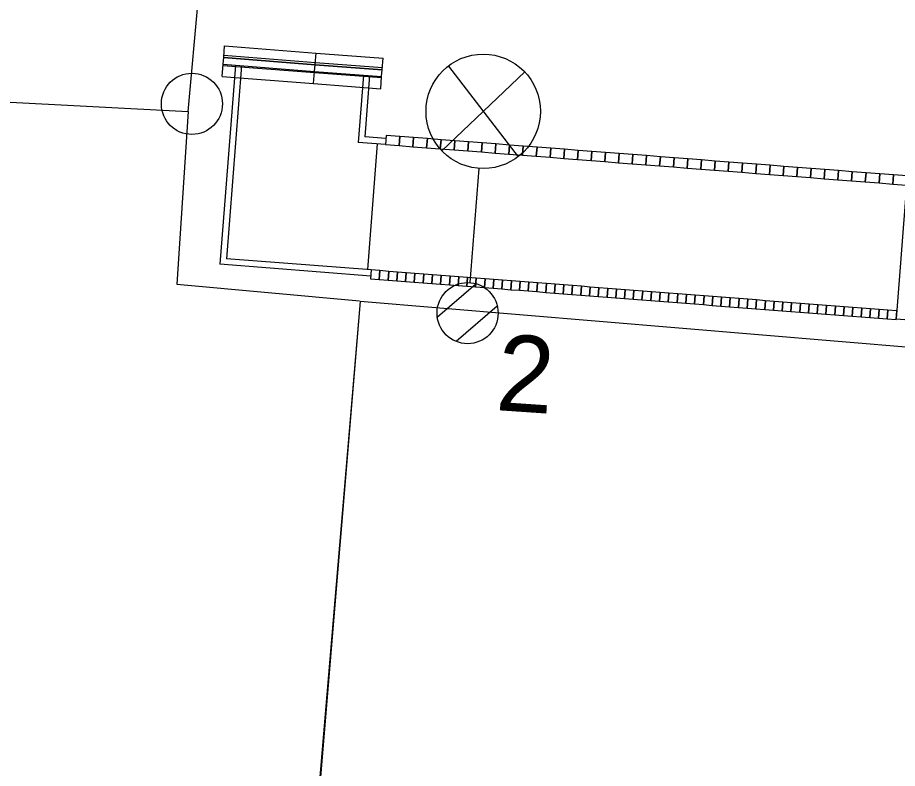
# Model space of a CAD drawing. Extents: x -669628 to -669207, y -977198 to -977075.
# Drawn here: x -669522.25 to -669510.73, y -977152.89 to -977143.06 of the extents above; entities that cross this region are included whole.
import ezdxf

# ---------------------------------------------------------------- set-up
doc = ezdxf.new("R2010")
doc.units = 0
for name, color, linetype in [('SO 01-86-01', 7, 'Continuous'), ('SO 11-11-01', 7, 'Continuous'), ('SO 11-12-01', 7, 'Continuous')]:
    doc.layers.add(name, color=color, linetype=linetype)

# ---------------------------------------------------------------- blocks, each defined once
blk = doc.blocks.new('POINT_DISPLAY')
blk.add_line((0, 0), (0, 0))

msp = doc.modelspace()

# ---------------------------------------------------------------- linework, layer by layer
at = {"layer": 'SO 01-86-01'}
for p, q in [((-669520.014, -977144.295), (-669519.163, -977134.751)), ((-669539.545, -977143.259), (-669520.014, -977144.295)), ((-669516.607, -977143.698), (-669515.695, -977144.885)), ((-669516.693, -977144.807), (-669515.608, -977143.775)), ((-669520.014, -977144.295), (-669520.162, -977146.551)), ((-669516.209, -977145.037), (-669516.325, -977146.533)), ((-669520.162, -977146.551), (-669517.772, -977146.771)), ((-669516.75, -977146.981), (-669516.246, -977146.55)), ((-669517.763, -977146.78), (-669518.52, -977155.707)), ((-669517.763, -977146.78), (-669518.507, -977155.699)), ((-669517.763, -977146.78), (-669518.424, -977154.562)), ((-669445.341, -977152.857), (-669517.763, -977146.78)), ((-669445.341, -977152.857), (-669517.763, -977146.78)), ((-669443.485, -977152.976), (-669517.763, -977146.78)), ((-669516.506, -977147.298), (-669515.969, -977146.838))]:
    msp.add_line(p, q, dxfattribs=at)
for centre, radius in [((-669516.151, -977144.291), 0.749), ((-669519.965, -977144.193), 0.4), ((-669516.356, -977146.932), 0.4)]:
    msp.add_circle(centre, radius, dxfattribs=at)
at = {"layer": 'SO 11-11-01'}
for p, q in [((-669519.548, -977143.584), (-669519.536, -977143.435)), ((-669519.536, -977143.435), (-669518.34, -977143.529)), ((-669518.351, -977143.677), (-669518.34, -977143.529)), ((-669518.351, -977143.677), (-669518.34, -977143.529)), ((-669518.34, -977143.529), (-669517.462, -977143.597)), ((-669519.555, -977143.675), (-669519.548, -977143.584)), ((-669519.548, -977143.584), (-669518.351, -977143.677)), ((-669519.548, -977143.588), (-669518.352, -977143.681)), ((-669519.546, -977143.558), (-669518.349, -977143.651)), ((-669518.349, -977143.651), (-669517.472, -977143.719)), ((-669517.474, -977143.745), (-669517.462, -977143.597)), ((-669519.567, -977143.834), (-669519.555, -977143.675)), ((-669519.556, -977143.689), (-669518.359, -977143.782)), ((-669519.555, -977143.675), (-669518.358, -977143.768)), ((-669518.358, -977143.768), (-669518.351, -977143.677)), ((-669518.358, -977143.768), (-669518.351, -977143.677)), ((-669518.352, -977143.681), (-669517.474, -977143.749)), ((-669518.351, -977143.677), (-669517.474, -977143.745)), ((-669517.481, -977143.836), (-669517.474, -977143.745)), ((-669519.567, -977143.834), (-669518.371, -977143.927)), ((-669518.371, -977143.927), (-669518.358, -977143.768)), ((-669518.371, -977143.927), (-669518.358, -977143.768)), ((-669518.359, -977143.782), (-669517.482, -977143.85)), ((-669518.358, -977143.768), (-669517.481, -977143.836)), ((-669517.493, -977143.996), (-669517.481, -977143.836)), ((-669518.371, -977143.927), (-669517.493, -977143.996))]:
    msp.add_line(p, q, dxfattribs=at)
at = {"layer": 'SO 11-12-01'}
for p, q in [((-669519.395, -977143.687), (-669519.598, -977146.293)), ((-669519.315, -977143.693), (-669519.512, -977146.22)), ((-669517.72, -977143.818), (-669517.789, -977144.698)), ((-669517.641, -977143.824), (-669517.703, -977144.624)), ((-669510.545, -977144.409), (-669510.747, -977147.008)), ((-669517.425, -977144.646), (-669517.703, -977144.624)), ((-669517.421, -977144.606), (-669517.431, -977144.726)), ((-669517.242, -977144.62), (-669517.421, -977144.606)), ((-669517.251, -977144.74), (-669517.242, -977144.62)), ((-669517.242, -977144.62), (-669517.251, -977144.74)), ((-669517.062, -977144.634), (-669517.242, -977144.62)), ((-669517.072, -977144.754), (-669517.062, -977144.634)), ((-669517.062, -977144.634), (-669517.072, -977144.754)), ((-669516.883, -977144.648), (-669517.062, -977144.634)), ((-669516.892, -977144.768), (-669516.883, -977144.648)), ((-669516.883, -977144.648), (-669516.892, -977144.768)), ((-669516.704, -977144.662), (-669516.883, -977144.648)), ((-669516.713, -977144.781), (-669516.704, -977144.662)), ((-669516.704, -977144.662), (-669516.713, -977144.781)), ((-669516.524, -977144.676), (-669516.704, -977144.662)), ((-669516.524, -977144.676), (-669516.533, -977144.795)), ((-669516.533, -977144.795), (-669516.524, -977144.676)), ((-669516.345, -977144.69), (-669516.524, -977144.676)), ((-669517.431, -977144.726), (-669517.789, -977144.698)), ((-669517.54, -977144.717), (-669517.668, -977146.363)), ((-669517.431, -977144.726), (-669517.251, -977144.74)), ((-669517.251, -977144.74), (-669517.072, -977144.754)), ((-669517.072, -977144.754), (-669516.892, -977144.768)), ((-669516.892, -977144.768), (-669516.713, -977144.781)), ((-669516.713, -977144.781), (-669516.533, -977144.795)), ((-669516.533, -977144.795), (-669516.354, -977144.809)), ((-669516.345, -977144.69), (-669516.354, -977144.809)), ((-669516.354, -977144.809), (-669516.345, -977144.69)), ((-669516.165, -977144.704), (-669516.345, -977144.69)), ((-669516.165, -977144.704), (-669516.175, -977144.823)), ((-669516.175, -977144.823), (-669516.165, -977144.704)), ((-669515.986, -977144.718), (-669516.165, -977144.704)), ((-669515.986, -977144.718), (-669515.995, -977144.837)), ((-669515.995, -977144.837), (-669515.986, -977144.718)), ((-669515.806, -977144.732), (-669515.986, -977144.718)), ((-669515.806, -977144.732), (-669515.816, -977144.851)), ((-669515.816, -977144.851), (-669515.806, -977144.732)), ((-669515.627, -977144.746), (-669515.806, -977144.732)), ((-669515.627, -977144.746), (-669515.636, -977144.865)), ((-669515.636, -977144.865), (-669515.627, -977144.746)), ((-669515.447, -977144.76), (-669515.627, -977144.746)), ((-669515.447, -977144.76), (-669515.457, -977144.879)), ((-669515.457, -977144.879), (-669515.447, -977144.76)), ((-669515.268, -977144.774), (-669515.447, -977144.76)), ((-669515.268, -977144.774), (-669515.277, -977144.893)), ((-669515.277, -977144.893), (-669515.268, -977144.774)), ((-669515.088, -977144.788), (-669515.268, -977144.774)), ((-669515.088, -977144.788), (-669515.098, -977144.907)), ((-669515.098, -977144.907), (-669515.088, -977144.788)), ((-669514.909, -977144.802), (-669515.088, -977144.788)), ((-669514.909, -977144.802), (-669514.918, -977144.921)), ((-669514.918, -977144.921), (-669514.909, -977144.802)), ((-669514.73, -977144.816), (-669514.909, -977144.802)), ((-669516.354, -977144.809), (-669516.175, -977144.823)), ((-669516.175, -977144.823), (-669515.995, -977144.837)), ((-669515.995, -977144.837), (-669515.816, -977144.851)), ((-669515.816, -977144.851), (-669515.636, -977144.865)), ((-669515.636, -977144.865), (-669515.457, -977144.879)), ((-669515.457, -977144.879), (-669515.277, -977144.893)), ((-669515.277, -977144.893), (-669515.098, -977144.907)), ((-669515.098, -977144.907), (-669514.918, -977144.921)), ((-669514.73, -977144.816), (-669514.739, -977144.935)), ((-669514.739, -977144.935), (-669514.73, -977144.816)), ((-669514.55, -977144.829), (-669514.73, -977144.816)), ((-669514.55, -977144.829), (-669514.559, -977144.949)), ((-669514.559, -977144.949), (-669514.55, -977144.829)), ((-669514.371, -977144.843), (-669514.55, -977144.829)), ((-669514.371, -977144.843), (-669514.38, -977144.963)), ((-669514.38, -977144.963), (-669514.371, -977144.843)), ((-669514.191, -977144.857), (-669514.371, -977144.843)), ((-669514.191, -977144.857), (-669514.2, -977144.977)), ((-669514.2, -977144.977), (-669514.191, -977144.857)), ((-669514.012, -977144.871), (-669514.191, -977144.857)), ((-669514.012, -977144.871), (-669514.021, -977144.991)), ((-669514.021, -977144.991), (-669514.012, -977144.871)), ((-669513.832, -977144.885), (-669514.012, -977144.871)), ((-669513.832, -977144.885), (-669513.842, -977145.005)), ((-669513.842, -977145.005), (-669513.832, -977144.885)), ((-669513.653, -977144.899), (-669513.832, -977144.885)), ((-669513.653, -977144.899), (-669513.662, -977145.019)), ((-669513.662, -977145.019), (-669513.653, -977144.899)), ((-669513.473, -977144.913), (-669513.653, -977144.899)), ((-669513.473, -977144.913), (-669513.483, -977145.033)), ((-669513.483, -977145.033), (-669513.473, -977144.913)), ((-669513.294, -977144.927), (-669513.473, -977144.913)), ((-669514.918, -977144.921), (-669514.739, -977144.935)), ((-669514.739, -977144.935), (-669514.559, -977144.949)), ((-669514.559, -977144.949), (-669514.38, -977144.963)), ((-669514.38, -977144.963), (-669514.2, -977144.977)), ((-669514.2, -977144.977), (-669514.021, -977144.991)), ((-669514.021, -977144.991), (-669513.842, -977145.005)), ((-669513.842, -977145.005), (-669513.662, -977145.019)), ((-669513.662, -977145.019), (-669513.483, -977145.033)), ((-669513.483, -977145.033), (-669513.303, -977145.047)), ((-669513.294, -977144.927), (-669513.303, -977145.047)), ((-669513.303, -977145.047), (-669513.294, -977144.927)), ((-669513.114, -977144.941), (-669513.294, -977144.927)), ((-669513.114, -977144.941), (-669513.124, -977145.061)), ((-669513.124, -977145.061), (-669513.114, -977144.941)), ((-669512.935, -977144.955), (-669513.114, -977144.941)), ((-669512.935, -977144.955), (-669512.944, -977145.075)), ((-669512.944, -977145.075), (-669512.935, -977144.955)), ((-669512.756, -977144.969), (-669512.935, -977144.955)), ((-669512.756, -977144.969), (-669512.765, -977145.089)), ((-669512.765, -977145.089), (-669512.756, -977144.969)), ((-669512.576, -977144.983), (-669512.756, -977144.969)), ((-669512.576, -977144.983), (-669512.585, -977145.103)), ((-669512.585, -977145.103), (-669512.576, -977144.983)), ((-669512.397, -977144.997), (-669512.576, -977144.983)), ((-669512.397, -977144.997), (-669512.406, -977145.117)), ((-669512.406, -977145.117), (-669512.397, -977144.997)), ((-669512.217, -977145.011), (-669512.397, -977144.997)), ((-669512.217, -977145.011), (-669512.226, -977145.131)), ((-669512.226, -977145.131), (-669512.217, -977145.011)), ((-669512.038, -977145.025), (-669512.217, -977145.011)), ((-669512.038, -977145.025), (-669512.047, -977145.145)), ((-669512.047, -977145.145), (-669512.038, -977145.025)), ((-669511.858, -977145.039), (-669512.038, -977145.025)), ((-669513.303, -977145.047), (-669513.124, -977145.061)), ((-669513.124, -977145.061), (-669512.944, -977145.075)), ((-669512.944, -977145.075), (-669512.765, -977145.089)), ((-669512.765, -977145.089), (-669512.585, -977145.103)), ((-669512.585, -977145.103), (-669512.406, -977145.117)), ((-669512.406, -977145.117), (-669512.226, -977145.131)), ((-669512.226, -977145.131), (-669512.047, -977145.145)), ((-669512.047, -977145.145), (-669511.868, -977145.159)), ((-669511.858, -977145.039), (-669511.868, -977145.159)), ((-669511.868, -977145.159), (-669511.858, -977145.039)), ((-669511.679, -977145.053), (-669511.858, -977145.039)), ((-669511.679, -977145.053), (-669511.688, -977145.173)), ((-669511.688, -977145.173), (-669511.679, -977145.053)), ((-669511.499, -977145.067), (-669511.679, -977145.053)), ((-669511.499, -977145.067), (-669511.509, -977145.187)), ((-669511.509, -977145.187), (-669511.499, -977145.067)), ((-669511.32, -977145.081), (-669511.499, -977145.067)), ((-669511.32, -977145.081), (-669511.329, -977145.201)), ((-669511.329, -977145.201), (-669511.32, -977145.081)), ((-669511.14, -977145.095), (-669511.32, -977145.081)), ((-669511.14, -977145.095), (-669511.15, -977145.215)), ((-669511.15, -977145.215), (-669511.14, -977145.095)), ((-669510.961, -977145.109), (-669511.14, -977145.095)), ((-669510.961, -977145.109), (-669510.97, -977145.228)), ((-669510.97, -977145.228), (-669510.961, -977145.109)), ((-669510.781, -977145.123), (-669510.961, -977145.109)), ((-669510.781, -977145.123), (-669510.791, -977145.242)), ((-669510.791, -977145.242), (-669510.781, -977145.123)), ((-669510.602, -977145.137), (-669510.781, -977145.123)), ((-669511.868, -977145.159), (-669511.688, -977145.173)), ((-669511.688, -977145.173), (-669511.509, -977145.187)), ((-669511.509, -977145.187), (-669511.329, -977145.201)), ((-669511.329, -977145.201), (-669511.15, -977145.215)), ((-669511.15, -977145.215), (-669510.97, -977145.228)), ((-669510.97, -977145.228), (-669510.791, -977145.242)), ((-669510.791, -977145.242), (-669510.611, -977145.256)), ((-669517.624, -977146.447), (-669519.598, -977146.293)), ((-669517.618, -977146.367), (-669519.512, -977146.22)), ((-669517.618, -977146.367), (-669517.627, -977146.482)), ((-669517.503, -977146.376), (-669517.618, -977146.367)), ((-669517.503, -977146.376), (-669517.512, -977146.491)), ((-669517.512, -977146.491), (-669517.503, -977146.376)), ((-669517.389, -977146.385), (-669517.503, -977146.376)), ((-669517.389, -977146.385), (-669517.397, -977146.5)), ((-669517.397, -977146.5), (-669517.389, -977146.385)), ((-669517.274, -977146.394), (-669517.389, -977146.385)), ((-669517.274, -977146.394), (-669517.283, -977146.509)), ((-669517.283, -977146.509), (-669517.274, -977146.394)), ((-669517.159, -977146.403), (-669517.274, -977146.394)), ((-669517.159, -977146.403), (-669517.168, -977146.517)), ((-669517.168, -977146.517), (-669517.159, -977146.403)), ((-669517.045, -977146.412), (-669517.159, -977146.403)), ((-669517.045, -977146.412), (-669517.054, -977146.526)), ((-669517.054, -977146.526), (-669517.045, -977146.412)), ((-669516.93, -977146.421), (-669517.045, -977146.412)), ((-669517.627, -977146.482), (-669517.512, -977146.491)), ((-669517.512, -977146.491), (-669517.397, -977146.5)), ((-669517.397, -977146.5), (-669517.283, -977146.509)), ((-669517.283, -977146.509), (-669517.168, -977146.517)), ((-669517.168, -977146.517), (-669517.054, -977146.526)), ((-669517.054, -977146.526), (-669516.939, -977146.535)), ((-669516.939, -977146.535), (-669516.93, -977146.421)), ((-669516.93, -977146.421), (-669516.939, -977146.535)), ((-669516.815, -977146.43), (-669516.93, -977146.421)), ((-669516.824, -977146.544), (-669516.815, -977146.43)), ((-669516.815, -977146.43), (-669516.824, -977146.544)), ((-669516.701, -977146.438), (-669516.815, -977146.43)), ((-669516.71, -977146.553), (-669516.701, -977146.438)), ((-669516.701, -977146.438), (-669516.71, -977146.553)), ((-669516.586, -977146.447), (-669516.701, -977146.438)), ((-669516.595, -977146.562), (-669516.586, -977146.447)), ((-669516.586, -977146.447), (-669516.595, -977146.562)), ((-669516.471, -977146.456), (-669516.586, -977146.447)), ((-669516.48, -977146.571), (-669516.471, -977146.456)), ((-669516.471, -977146.456), (-669516.48, -977146.571)), ((-669516.357, -977146.465), (-669516.471, -977146.456)), ((-669516.366, -977146.58), (-669516.357, -977146.465)), ((-669516.357, -977146.465), (-669516.366, -977146.58)), ((-669516.242, -977146.474), (-669516.357, -977146.465)), ((-669516.251, -977146.589), (-669516.242, -977146.474)), ((-669516.242, -977146.474), (-669516.251, -977146.589)), ((-669516.127, -977146.483), (-669516.242, -977146.474)), ((-669516.136, -977146.598), (-669516.127, -977146.483)), ((-669516.127, -977146.483), (-669516.136, -977146.598)), ((-669516.013, -977146.492), (-669516.127, -977146.483)), ((-669516.022, -977146.607), (-669516.013, -977146.492)), ((-669516.013, -977146.492), (-669516.022, -977146.607)), ((-669515.898, -977146.501), (-669516.013, -977146.492)), ((-669515.907, -977146.616), (-669515.898, -977146.501)), ((-669515.898, -977146.501), (-669515.907, -977146.616)), ((-669515.783, -977146.51), (-669515.898, -977146.501)), ((-669515.792, -977146.625), (-669515.783, -977146.51)), ((-669515.783, -977146.51), (-669515.792, -977146.625)), ((-669515.669, -977146.519), (-669515.783, -977146.51)), ((-669515.678, -977146.633), (-669515.669, -977146.519)), ((-669515.669, -977146.519), (-669515.678, -977146.633)), ((-669515.554, -977146.528), (-669515.669, -977146.519)), ((-669515.563, -977146.642), (-669515.554, -977146.528)), ((-669515.554, -977146.528), (-669515.563, -977146.642)), ((-669515.439, -977146.537), (-669515.554, -977146.528)), ((-669516.939, -977146.535), (-669516.824, -977146.544)), ((-669516.824, -977146.544), (-669516.71, -977146.553)), ((-669516.71, -977146.553), (-669516.595, -977146.562)), ((-669516.595, -977146.562), (-669516.48, -977146.571)), ((-669516.48, -977146.571), (-669516.366, -977146.58)), ((-669516.366, -977146.58), (-669516.251, -977146.589)), ((-669516.251, -977146.589), (-669516.136, -977146.598)), ((-669516.136, -977146.598), (-669516.022, -977146.607)), ((-669516.022, -977146.607), (-669515.907, -977146.616)), ((-669515.907, -977146.616), (-669515.792, -977146.625)), ((-669515.792, -977146.625), (-669515.678, -977146.633)), ((-669515.678, -977146.633), (-669515.563, -977146.642)), ((-669515.563, -977146.642), (-669515.448, -977146.651)), ((-669515.448, -977146.651), (-669515.439, -977146.537)), ((-669515.439, -977146.537), (-669515.448, -977146.651)), ((-669515.325, -977146.546), (-669515.439, -977146.537)), ((-669515.334, -977146.66), (-669515.325, -977146.546)), ((-669515.325, -977146.546), (-669515.334, -977146.66)), ((-669515.21, -977146.555), (-669515.325, -977146.546)), ((-669515.219, -977146.669), (-669515.21, -977146.555)), ((-669515.21, -977146.555), (-669515.219, -977146.669)), ((-669515.096, -977146.563), (-669515.21, -977146.555)), ((-669515.104, -977146.678), (-669515.096, -977146.563)), ((-669515.096, -977146.563), (-669515.104, -977146.678)), ((-669514.981, -977146.572), (-669515.096, -977146.563)), ((-669514.99, -977146.687), (-669514.981, -977146.572)), ((-669514.981, -977146.572), (-669514.99, -977146.687)), ((-669514.866, -977146.581), (-669514.981, -977146.572)), ((-669514.875, -977146.696), (-669514.866, -977146.581)), ((-669514.866, -977146.581), (-669514.875, -977146.696)), ((-669514.752, -977146.59), (-669514.866, -977146.581)), ((-669514.76, -977146.705), (-669514.752, -977146.59)), ((-669514.752, -977146.59), (-669514.76, -977146.705)), ((-669514.637, -977146.599), (-669514.752, -977146.59)), ((-669514.646, -977146.714), (-669514.637, -977146.599)), ((-669514.637, -977146.599), (-669514.646, -977146.714)), ((-669514.522, -977146.608), (-669514.637, -977146.599)), ((-669514.531, -977146.723), (-669514.522, -977146.608)), ((-669514.522, -977146.608), (-669514.531, -977146.723)), ((-669514.408, -977146.617), (-669514.522, -977146.608)), ((-669514.417, -977146.732), (-669514.408, -977146.617)), ((-669514.408, -977146.617), (-669514.417, -977146.732)), ((-669514.293, -977146.626), (-669514.408, -977146.617)), ((-669514.302, -977146.741), (-669514.293, -977146.626)), ((-669514.293, -977146.626), (-669514.302, -977146.741)), ((-669514.178, -977146.635), (-669514.293, -977146.626)), ((-669514.187, -977146.749), (-669514.178, -977146.635)), ((-669514.178, -977146.635), (-669514.187, -977146.749)), ((-669514.064, -977146.644), (-669514.178, -977146.635)), ((-669514.073, -977146.758), (-669514.064, -977146.644)), ((-669514.064, -977146.644), (-669514.073, -977146.758)), ((-669513.949, -977146.653), (-669514.064, -977146.644)), ((-669515.448, -977146.651), (-669515.334, -977146.66)), ((-669515.334, -977146.66), (-669515.219, -977146.669)), ((-669515.219, -977146.669), (-669515.104, -977146.678)), ((-669515.104, -977146.678), (-669514.99, -977146.687)), ((-669514.99, -977146.687), (-669514.875, -977146.696)), ((-669514.875, -977146.696), (-669514.76, -977146.705)), ((-669514.76, -977146.705), (-669514.646, -977146.714)), ((-669514.646, -977146.714), (-669514.531, -977146.723)), ((-669514.531, -977146.723), (-669514.417, -977146.732)), ((-669514.417, -977146.732), (-669514.302, -977146.741)), ((-669514.302, -977146.741), (-669514.187, -977146.749)), ((-669514.187, -977146.749), (-669514.073, -977146.758)), ((-669514.073, -977146.758), (-669513.958, -977146.767)), ((-669513.958, -977146.767), (-669513.949, -977146.653)), ((-669513.949, -977146.653), (-669513.958, -977146.767)), ((-669513.834, -977146.662), (-669513.949, -977146.653)), ((-669513.843, -977146.776), (-669513.834, -977146.662)), ((-669513.834, -977146.662), (-669513.843, -977146.776)), ((-669513.72, -977146.671), (-669513.834, -977146.662)), ((-669513.729, -977146.785), (-669513.72, -977146.671)), ((-669513.72, -977146.671), (-669513.729, -977146.785)), ((-669513.605, -977146.679), (-669513.72, -977146.671)), ((-669513.614, -977146.794), (-669513.605, -977146.679)), ((-669513.605, -977146.679), (-669513.614, -977146.794)), ((-669513.49, -977146.688), (-669513.605, -977146.679)), ((-669513.499, -977146.803), (-669513.49, -977146.688)), ((-669513.49, -977146.688), (-669513.499, -977146.803)), ((-669513.376, -977146.697), (-669513.49, -977146.688)), ((-669513.385, -977146.812), (-669513.376, -977146.697)), ((-669513.376, -977146.697), (-669513.385, -977146.812)), ((-669513.261, -977146.706), (-669513.376, -977146.697)), ((-669513.27, -977146.821), (-669513.261, -977146.706)), ((-669513.261, -977146.706), (-669513.27, -977146.821)), ((-669513.146, -977146.715), (-669513.261, -977146.706)), ((-669513.155, -977146.83), (-669513.146, -977146.715)), ((-669513.146, -977146.715), (-669513.155, -977146.83)), ((-669513.032, -977146.724), (-669513.146, -977146.715)), ((-669513.041, -977146.839), (-669513.032, -977146.724)), ((-669513.032, -977146.724), (-669513.041, -977146.839)), ((-669512.917, -977146.733), (-669513.032, -977146.724)), ((-669512.926, -977146.848), (-669512.917, -977146.733)), ((-669512.917, -977146.733), (-669512.926, -977146.848)), ((-669512.802, -977146.742), (-669512.917, -977146.733)), ((-669512.811, -977146.857), (-669512.802, -977146.742)), ((-669512.802, -977146.742), (-669512.811, -977146.857)), ((-669512.688, -977146.751), (-669512.802, -977146.742)), ((-669512.697, -977146.866), (-669512.688, -977146.751)), ((-669512.688, -977146.751), (-669512.697, -977146.866)), ((-669512.573, -977146.76), (-669512.688, -977146.751)), ((-669512.582, -977146.874), (-669512.573, -977146.76)), ((-669512.573, -977146.76), (-669512.582, -977146.874)), ((-669512.458, -977146.769), (-669512.573, -977146.76)), ((-669513.958, -977146.767), (-669513.843, -977146.776)), ((-669513.843, -977146.776), (-669513.729, -977146.785)), ((-669513.729, -977146.785), (-669513.614, -977146.794)), ((-669513.614, -977146.794), (-669513.499, -977146.803)), ((-669513.499, -977146.803), (-669513.385, -977146.812)), ((-669513.385, -977146.812), (-669513.27, -977146.821)), ((-669513.27, -977146.821), (-669513.155, -977146.83)), ((-669513.155, -977146.83), (-669513.041, -977146.839)), ((-669513.041, -977146.839), (-669512.926, -977146.848)), ((-669512.926, -977146.848), (-669512.811, -977146.857)), ((-669512.811, -977146.857), (-669512.697, -977146.866)), ((-669512.697, -977146.866), (-669512.582, -977146.874)), ((-669512.582, -977146.874), (-669512.467, -977146.883)), ((-669512.467, -977146.883), (-669512.458, -977146.769)), ((-669512.458, -977146.769), (-669512.467, -977146.883)), ((-669512.344, -977146.778), (-669512.458, -977146.769)), ((-669512.353, -977146.892), (-669512.344, -977146.778)), ((-669512.344, -977146.778), (-669512.353, -977146.892)), ((-669512.229, -977146.787), (-669512.344, -977146.778)), ((-669512.238, -977146.901), (-669512.229, -977146.787)), ((-669512.229, -977146.787), (-669512.238, -977146.901)), ((-669512.115, -977146.795), (-669512.229, -977146.787)), ((-669512.123, -977146.91), (-669512.115, -977146.795)), ((-669512.115, -977146.795), (-669512.123, -977146.91)), ((-669512, -977146.804), (-669512.115, -977146.795)), ((-669512.009, -977146.919), (-669512, -977146.804)), ((-669512, -977146.804), (-669512.009, -977146.919)), ((-669511.885, -977146.813), (-669512, -977146.804)), ((-669511.894, -977146.928), (-669511.885, -977146.813)), ((-669511.885, -977146.813), (-669511.894, -977146.928)), ((-669511.771, -977146.822), (-669511.885, -977146.813)), ((-669511.779, -977146.937), (-669511.771, -977146.822)), ((-669511.771, -977146.822), (-669511.779, -977146.937)), ((-669511.656, -977146.831), (-669511.771, -977146.822)), ((-669511.665, -977146.946), (-669511.656, -977146.831)), ((-669511.656, -977146.831), (-669511.665, -977146.946)), ((-669511.541, -977146.84), (-669511.656, -977146.831)), ((-669511.55, -977146.955), (-669511.541, -977146.84)), ((-669511.541, -977146.84), (-669511.55, -977146.955)), ((-669511.427, -977146.849), (-669511.541, -977146.84)), ((-669511.436, -977146.964), (-669511.427, -977146.849)), ((-669511.427, -977146.849), (-669511.436, -977146.964)), ((-669511.312, -977146.858), (-669511.427, -977146.849)), ((-669511.321, -977146.973), (-669511.312, -977146.858)), ((-669511.312, -977146.858), (-669511.321, -977146.973)), ((-669511.197, -977146.867), (-669511.312, -977146.858)), ((-669511.206, -977146.982), (-669511.197, -977146.867)), ((-669511.197, -977146.867), (-669511.206, -977146.982)), ((-669511.083, -977146.876), (-669511.197, -977146.867)), ((-669511.092, -977146.99), (-669511.083, -977146.876)), ((-669511.083, -977146.876), (-669511.092, -977146.99)), ((-669510.968, -977146.885), (-669511.083, -977146.876)), ((-669512.467, -977146.883), (-669512.353, -977146.892)), ((-669512.353, -977146.892), (-669512.238, -977146.901)), ((-669512.238, -977146.901), (-669512.123, -977146.91)), ((-669512.123, -977146.91), (-669512.009, -977146.919)), ((-669512.009, -977146.919), (-669511.894, -977146.928)), ((-669511.894, -977146.928), (-669511.779, -977146.937)), ((-669511.779, -977146.937), (-669511.665, -977146.946)), ((-669511.665, -977146.946), (-669511.55, -977146.955)), ((-669511.55, -977146.955), (-669511.436, -977146.964)), ((-669511.436, -977146.964), (-669511.321, -977146.973)), ((-669511.321, -977146.973), (-669511.206, -977146.982)), ((-669511.206, -977146.982), (-669511.092, -977146.99)), ((-669511.092, -977146.99), (-669510.977, -977146.999)), ((-669510.977, -977146.999), (-669510.968, -977146.885)), ((-669510.968, -977146.885), (-669510.977, -977146.999)), ((-669510.853, -977146.894), (-669510.968, -977146.885)), ((-669510.862, -977147.008), (-669510.853, -977146.894)), ((-669510.853, -977146.894), (-669510.862, -977147.008)), ((-669510.739, -977146.903), (-669510.853, -977146.894)), ((-669510.748, -977147.017), (-669510.739, -977146.903)), ((-669510.977, -977146.999), (-669510.862, -977147.008)), ((-669510.862, -977147.008), (-669510.748, -977147.017)), ((-669510.747, -977147.008), (-669508.738, -977147.161))]:
    msp.add_line(p, q, dxfattribs=at)

# ---------------------------------------------------------------- block references
at = {"layer": 'SO 01-86-01', "rotation": -4.450857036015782}
msp.add_blockref('POINT_DISPLAY', (-669516.356, -977146.932), dxfattribs=at)

# ---------------------------------------------------------------- texts
at = {"layer": 'SO 01-86-01'}
msp.add_text('2', height=1, rotation=356.1, dxfattribs=at).set_placement((-669516, -977148.2))

doc.saveas('drawing.dxf')
